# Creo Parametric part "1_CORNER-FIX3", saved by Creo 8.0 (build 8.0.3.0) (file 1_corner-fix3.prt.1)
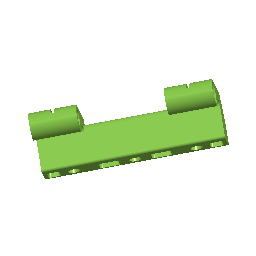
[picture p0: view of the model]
Units: millimeter Newton Second (mmNs); MM, TONNE, SECS

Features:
  1. datum plane "RIGHT"
  2. datum plane "TOP"
  3. datum plane "FRONT"
  4. coordinate system
  5. protrusion
  6. cut
  7. cut
  8. cut
  9. cut
  10. cut
  11. cut
  12. cut
  13. protrusion
  14. datum plane "DTM1"
  15. datum plane "DTM2"
  16. protrusion
  17. protrusion
  18. datum plane "DTM3"
  19. protrusion
  20. chamfer
  21. cut
  22. round
  23. round
  24. round

Other named items: COPIED_GROUP, COPIED_GROUP_1

Layers: 0_ALL_AXIS, 0_ALL_CSYS, 0_ALL_CURVES, 0_ALL_PLANES, 0_ALL_POINTS, 0_ALL_SURFS, CL201

Surfaces: 37 plane, 18 cylinder, 12 fillet, 10 cone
